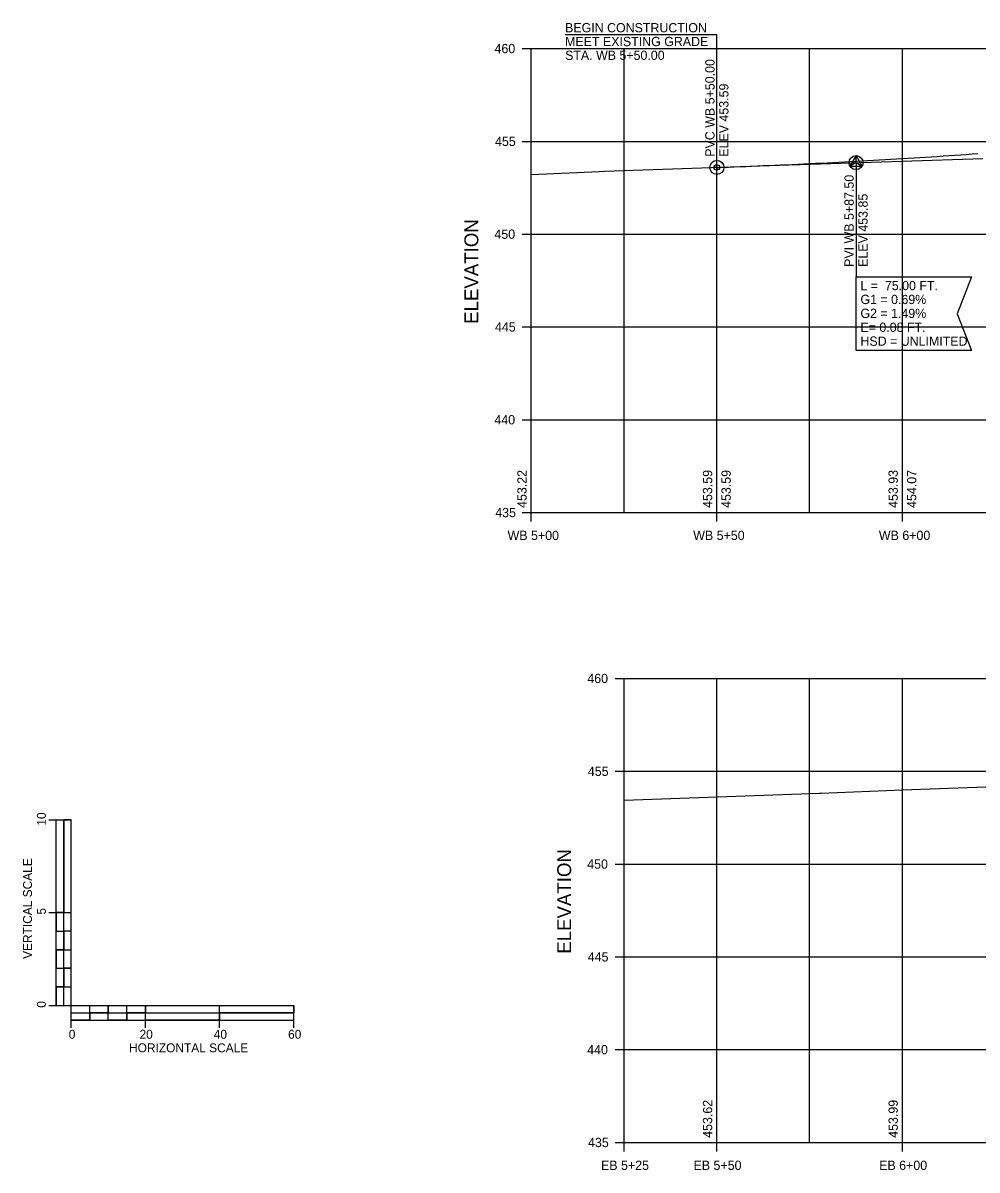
# Model space of a CAD drawing. Extents: x -1473 to -874, y -3319 to -2918.
# Drawn here: x -1472.8 to -1215.7, y -3252.3 to -2943.3 of the extents above; entities that cross this region are included whole.
import ezdxf

# ---------------------------------------------------------------- set-up
doc = ezdxf.new("R2010")
doc.units = 0
for name, color, linetype in [('Default', 7, 'Continuous'), ('NSB_P', 7, 'Continuous'), ('NSB_P_T', 7, 'Continuous'), ('XANNOT_P_T', 7, 'Continuous'), ('XAX_P', 7, 'Continuous'), ('XAXTIC_P', 7, 'Continuous'), ('XAXTXT_P_T', 7, 'Continuous'), ('XSLFG1_P', 7, 'Continuous'), ('XSLOG1', 7, 'Continuous')]:
    doc.layers.add(name, color=color, linetype=linetype)

msp = doc.modelspace()

# ---------------------------------------------------------------- linework, layer by layer
at = {"layer": 'NSB_P'}
for p, q in [((-1465.79, -3157.96), (-1459.79, -3157.96)), ((-1463.79, -3207.96), (-1463.79, -3157.96)), ((-1461.79, -3207.96), (-1461.79, -3157.96)), ((-1459.79, -3207.96), (-1459.79, -3157.96)), ((-1465.79, -3182.96), (-1459.79, -3182.96)), ((-1463.79, -3192.96), (-1459.79, -3192.96)), ((-1463.79, -3197.96), (-1459.79, -3197.96)), ((-1463.79, -3202.96), (-1461.79, -3202.96)), ((-1465.79, -3207.96), (-1459.79, -3207.96)), ((-1459.79, -3207.96), (-1399.79, -3207.96)), ((-1459.79, -3213.96), (-1459.79, -3207.96)), ((-1459.79, -3209.96), (-1399.79, -3209.96)), ((-1454.79, -3211.96), (-1454.79, -3209.96)), ((-1449.79, -3211.96), (-1449.79, -3207.96)), ((-1444.79, -3211.96), (-1444.79, -3207.96)), ((-1439.79, -3213.96), (-1439.79, -3207.96)), ((-1419.79, -3213.96), (-1419.79, -3207.96)), ((-1399.79, -3213.96), (-1399.79, -3207.96)), ((-1459.79, -3211.96), (-1399.79, -3211.96))]:
    msp.add_line(p, q, dxfattribs=at)
for points in [[(-1459.79, -3182.96), (-1459.79, -3157.96), (-1461.79, -3157.96), (-1461.79, -3182.96)], [(-1461.79, -3187.96), (-1461.79, -3182.96), (-1463.79, -3182.96), (-1463.79, -3187.96)], [(-1459.79, -3192.96), (-1459.79, -3187.96), (-1461.79, -3187.96), (-1461.79, -3192.96)], [(-1461.79, -3197.96), (-1461.79, -3192.96), (-1463.79, -3192.96), (-1463.79, -3197.96)], [(-1459.79, -3202.96), (-1459.79, -3197.96), (-1461.79, -3197.96), (-1461.79, -3202.96)], [(-1461.79, -3207.96), (-1461.79, -3202.96), (-1463.79, -3202.96), (-1463.79, -3207.96)], [(-1459.79, -3209.96), (-1454.79, -3209.96), (-1454.79, -3211.96), (-1459.79, -3211.96)], [(-1454.79, -3207.96), (-1449.79, -3207.96), (-1449.79, -3209.96), (-1454.79, -3209.96)], [(-1449.79, -3209.96), (-1444.79, -3209.96), (-1444.79, -3211.96), (-1449.79, -3211.96)], [(-1444.79, -3207.96), (-1439.79, -3207.96), (-1439.79, -3209.96), (-1444.79, -3209.96)], [(-1439.79, -3209.96), (-1419.79, -3209.96), (-1419.79, -3211.96), (-1439.79, -3211.96)], [(-1419.79, -3207.96), (-1399.79, -3207.96), (-1399.79, -3209.96), (-1419.79, -3209.96)]]:
    msp.add_lwpolyline(points, close=True, dxfattribs=at)
at = {"layer": 'XANNOT_P_T'}
for p, q in [((-1285.84, -2946.54), (-1326.72, -2946.54)), ((-1285.84, -2982.22), (-1285.84, -2946.54)), ((-1285.83, -2982.22), (-1285.83, -2981.47)), ((-1248.34, -2980.92), (-1249.97, -2981.87)), ((-1248.34, -2980.92), (-1248.34, -2979.04)), ((-1248.34, -2980.92), (-1248.34, -3011.68)), ((-1248.33, -2980.92), (-1246.71, -2981.87)), ((-1285.83, -2982.22), (-1286.58, -2982.22)), ((-1285.83, -2982.22), (-1285.83, -2982.96)), ((-1285.68, -2982.22), (-1285.09, -2982.22))]:
    msp.add_line(p, q, dxfattribs=at)
for points in [[(-1248.34, -2979.04), (-1249.97, -2981.87), (-1246.71, -2981.87)], [(-1248.34, -3011.68), (-1217.26, -3011.68), (-1221.08, -3021.63), (-1217.26, -3031.57), (-1248.34, -3031.57)]]:
    msp.add_lwpolyline(points, close=True, dxfattribs=at)
for centre, radius in [((-1285.83, -2982.22), 1.89), ((-1285.83, -2982.22), 0.744), ((-1285.83, -2982.22), 0.154), ((-1248.34, -2980.92), 1.88)]:
    msp.add_circle(centre, radius, dxfattribs=at)
at = {"layer": 'XAX_P'}
for p, q in [((-1335.84, -3075.19), (-1335.84, -2950.19)), ((-1335.84, -2950.19), (-885.84, -2950.19)), ((-1335.84, -2950.19), (-885.84, -2950.19)), ((-1310.84, -3075.19), (-1310.84, -2950.19)), ((-1285.84, -3075.19), (-1285.84, -2950.19)), ((-1260.84, -3075.19), (-1260.84, -2950.19)), ((-1235.84, -3075.19), (-1235.84, -2950.19)), ((-1335.84, -2975.19), (-885.84, -2975.19)), ((-1335.84, -3000.19), (-885.84, -3000.19)), ((-1335.84, -3025.19), (-885.84, -3025.19)), ((-1335.84, -3050.19), (-885.84, -3050.19)), ((-1335.84, -3075.19), (-885.84, -3075.19)), ((-1310.84, -3244.88), (-1310.84, -3119.88)), ((-1310.84, -3119.88), (-885.84, -3119.88)), ((-1310.84, -3119.88), (-885.84, -3119.88)), ((-1285.84, -3244.88), (-1285.84, -3119.88)), ((-1260.84, -3244.88), (-1260.84, -3119.88)), ((-1235.84, -3244.88), (-1235.84, -3119.88)), ((-1310.84, -3144.88), (-885.84, -3144.88)), ((-1310.84, -3169.88), (-885.84, -3169.88)), ((-1310.84, -3194.88), (-885.84, -3194.88)), ((-1310.84, -3219.88), (-885.84, -3219.88)), ((-1310.84, -3244.88), (-885.84, -3244.88))]:
    msp.add_line(p, q, dxfattribs=at)
at = {"layer": 'XAXTIC_P'}
for p, q in [((-1338.24, -2950.19), (-1333.44, -2950.19)), ((-1338.24, -2950.19), (-1333.44, -2950.19)), ((-1338.24, -2975.19), (-1333.44, -2975.19)), ((-1338.24, -3000.19), (-1333.44, -3000.19)), ((-1338.24, -3025.19), (-1333.44, -3025.19)), ((-1338.24, -3050.19), (-1333.44, -3050.19)), ((-1335.84, -3077.59), (-1335.84, -3072.79)), ((-1310.84, -3075.19), (-1310.84, -3073.99)), ((-1285.84, -3077.59), (-1285.84, -3072.79)), ((-1260.84, -3075.19), (-1260.84, -3073.99)), ((-1235.84, -3077.59), (-1235.84, -3072.79)), ((-1338.24, -3075.19), (-1333.44, -3075.19)), ((-1313.24, -3119.88), (-1308.44, -3119.88)), ((-1313.24, -3119.88), (-1308.44, -3119.88)), ((-1313.24, -3144.88), (-1308.44, -3144.88)), ((-1313.24, -3169.88), (-1308.44, -3169.88)), ((-1313.24, -3194.88), (-1308.44, -3194.88)), ((-1313.24, -3219.88), (-1308.44, -3219.88)), ((-1310.84, -3247.28), (-1310.84, -3242.48)), ((-1285.84, -3247.28), (-1285.84, -3242.48)), ((-1260.84, -3244.88), (-1260.84, -3243.68)), ((-1235.84, -3247.28), (-1235.84, -3242.48)), ((-1313.24, -3244.88), (-1308.44, -3244.88))]:
    msp.add_line(p, q, dxfattribs=at)
at = {"layer": 'XSLFG1_P'}
msp.add_lwpolyline([(-1285.84, -2982.22), (-1284.27, -2982.16), (-1282.71, -2982.11), (-1281.15, -2982.05), (-1279.59, -2981.99), (-1278.02, -2981.93), (-1276.46, -2981.87), (-1274.9, -2981.81), (-1273.34, -2981.74), (-1271.77, -2981.68), (-1270.21, -2981.61), (-1268.65, -2981.54), (-1267.09, -2981.48), (-1265.52, -2981.41), (-1263.96, -2981.33), (-1262.4, -2981.26), (-1260.84, -2981.19), (-1259.27, -2981.11), (-1257.71, -2981.04), (-1256.15, -2980.96), (-1254.59, -2980.88), (-1253.02, -2980.8), (-1251.46, -2980.72), (-1249.9, -2980.63), (-1246.77, -2980.46), (-1245.21, -2980.37), (-1243.65, -2980.29), (-1242.09, -2980.2), (-1240.52, -2980.11), (-1238.96, -2980.01), (-1237.4, -2979.92), (-1235.84, -2979.82), (-1234.27, -2979.73), (-1232.71, -2979.63), (-1231.15, -2979.53), (-1229.59, -2979.43), (-1228.02, -2979.33), (-1226.46, -2979.23), (-1224.9, -2979.12), (-1223.34, -2979.02), (-1221.77, -2978.91), (-1220.21, -2978.8), (-1218.65, -2978.69), (-1217.09, -2978.58), (-1215.52, -2978.47)], dxfattribs=at)
at = {"layer": 'XSLOG1'}
for points in [[(-1335.84, -2984.08), (-1317.47, -2983.31), (-1316.07, -2983.26), (-1263.84, -2981.46), (-1263.38, -2981.44), (-1235.98, -2980.57), (-1235.98, -2980.57), (-1214.14, -2979.84)], [(-1310.84, -3152.69), (-1258.21, -3150.75), (-1257.87, -3150.74), (-1235.84, -3149.93), (-1235.84, -3149.93), (-1205.9, -3148.83)]]:
    msp.add_lwpolyline(points, dxfattribs=at)

# ---------------------------------------------------------------- texts
at = {"layer": 'Default'}
msp.add_text('HORIZONTAL SCALE', height=2.4, rotation=360, dxfattribs=at).set_placement((-1444.18, -3220.59))
at = {"layer": 'NSB_P_T'}
for s, rotation, p in [('10', 90, (-1466.6, -3159.53)), ('VERTICAL SCALE', 90, (-1470.33, -3195.43)), ('5', 90, (-1466.6, -3183.5)), ('0', 90, (-1466.6, -3208.59)), ('0', 360, (-1460.42, -3216.94)), ('20', 360, (-1441.36, -3216.94)), ('40', 360, (-1421.36, -3216.94)), ('60', 360, (-1401.34, -3216.94)), ('HORIZONTAL SCALE', 360, (-1444.18, -3220.59))]:
    msp.add_text(s, height=2.4, rotation=rotation, dxfattribs=at).set_placement(p)
at = {"layer": 'XANNOT_P_T'}
for s, height, p in [('BEGIN CONSTRUCTION', 2.496, (-1326.72, -2945.83)), ('MEET EXISTING GRADE', 2.496, (-1326.72, -2949.54)), ('STA. WB 5+50.00', 2.496, (-1326.72, -2953.25)), ('L =  75.00 FT.', 2.496, (-1247.15, -3015.29)), ('G1 = 0.69%', 2.496, (-1247.15, -3019.03)), ('G2 = 1.49%', 2.496, (-1247.15, -3022.78)), ('E= 0.08 FT.', 2.496, (-1247.15, -3026.52)), ('HSD = UNLIMITED', 2.496, (-1247.15, -3030.26)), ('-', 0.048, (-1335.87, -3075.19)), ('-', 0.048, (-1310.87, -3244.88))]:
    msp.add_text(s, height=height, dxfattribs=at).set_placement(p)
for s, height, p in [('PVC WB 5+50.00', 2.5008, (-1286.46, -2979.34)), ('ELEV 453.59 ', 2.5008, (-1282.71, -2979.34)), ('PVI WB 5+87.50', 2.5008, (-1248.96, -3009.01)), ('ELEV 453.85', 2.5008, (-1245.21, -3009.01)), ('453.22', 2.501, (-1337.09, -3073.94)), ('453.59', 2.501, (-1287.09, -3073.94)), ('453.59', 2.501, (-1282.09, -3073.94)), ('453.93', 2.501, (-1237.09, -3073.94)), ('454.07', 2.501, (-1232.09, -3073.94)), ('453.62', 2.501, (-1287.09, -3243.63)), ('453.99', 2.501, (-1237.09, -3243.63))]:
    msp.add_text(s, height=height, rotation=90, dxfattribs=at).set_placement(p)
at = {"layer": 'XAXTXT_P_T'}
for s, p in [('460', (-1345.73, -2951.44)), ('460', (-1345.73, -2951.44)), ('455', (-1345.59, -2976.44)), ('450', (-1345.76, -3001.44)), ('445', (-1345.61, -3026.44)), ('440', (-1345.77, -3051.44)), ('435', (-1345.53, -3076.44)), ('WB 5+00', (-1342.21, -3082.59)), ('WB 5+50', (-1292.2, -3082.59)), ('WB 6+00', (-1242.19, -3082.59)), ('460', (-1320.73, -3121.13)), ('460', (-1320.73, -3121.13)), ('455', (-1320.59, -3146.13)), ('450', (-1320.76, -3171.13)), ('445', (-1320.61, -3196.13)), ('440', (-1320.77, -3221.13)), ('435', (-1320.53, -3246.13)), ('EB 5+25', (-1317.04, -3252.28)), ('EB 5+50', (-1292.12, -3252.28)), ('EB 6+00', (-1242.11, -3252.28))]:
    msp.add_text(s, height=2.501, dxfattribs=at).set_placement(p)
for p in [(-1350.09, -3024.35), (-1325.09, -3194.03)]:
    msp.add_text('ELEVATION', height=3.754, rotation=90, dxfattribs=at).set_placement(p)

doc.saveas('drawing.dxf')
